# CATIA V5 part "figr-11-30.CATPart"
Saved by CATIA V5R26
Part number: Part1
Bounding box of the stored display mesh (mm): x -205 to 53, y -75.374 to 75.374, z 0 to 37.54
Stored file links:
  D:\_Deepak\CATIA\CATIA V5-6R2016_Deepak\Resources\Part files\Partfiles\c11_catia_v5_6r2016_prt\figr-11-30.CATPart
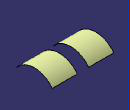
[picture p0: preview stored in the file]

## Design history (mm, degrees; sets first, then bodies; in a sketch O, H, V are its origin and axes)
Set1
  Extrude1: Element1 Sketch1, Lim1 53, Lim2 52, Direction yz-plane
  Translate1: ToTransfor Extrude1, Direction edge of Extrude1, Length 153
Body1 (main body)
  Sketch1 on yz-plane, origin (0, 0, 0), H (0, 1, 0), V (0, 0, 1)
    arc A1 centre (0, -56.4477) radius 94.1675 from (-75.3736, 0) to (75.3736, 0) cw
    point P1 (0, -56.4477)
    point P2 (-75.3736, 0)
    point P3 (75.3736, 0)
    point P4 (0, 37.7198)
    coincidence: P2 H, P3 H, A1 P4, P4 V, P1 V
